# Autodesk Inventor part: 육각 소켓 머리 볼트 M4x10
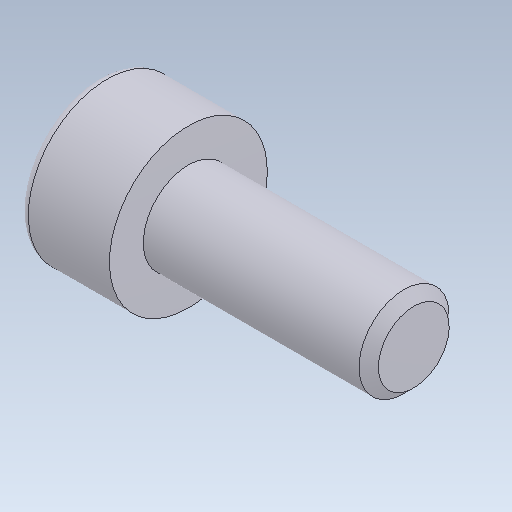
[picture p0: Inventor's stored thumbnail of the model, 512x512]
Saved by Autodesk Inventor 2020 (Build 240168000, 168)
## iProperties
Created: 2024-04
Part Number: 육각 소켓 머리 볼트 M4x10
Material: 강철, 연강
Description: 6각머리 태핑 나사
Document SubType Name: Modeling
Designer: oem
Density: 7.86 g/cm^3
Appearance: 기본값
Mass: 2.03689 g
Surface Area: 3.06255 cm^2
Volume: 0.259146 cm^3
Sending System: Autodesk Inventor 2025
Preprocessor: ST-DEVELOPER v20
Author: jhkim
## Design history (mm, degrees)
feature "Solid1"
node "솔리드1"
